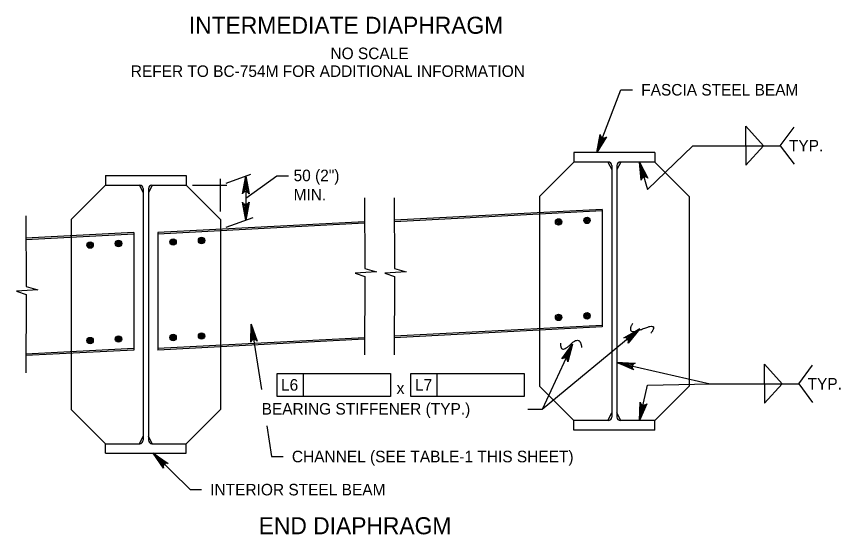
# Model space of a CAD drawing. Extents: x 638175 to 640495, y 294277 to 298435.
# Drawn here: x 639679.1 to 639893, y 297553.5 to 297688 of the extents above; entities that cross this region are included whole.
import ezdxf

# ---------------------------------------------------------------- set-up
doc = ezdxf.new("R2010")
doc.units = 0
for name, color, linetype in [('2', 7, 'Continuous'), ('3', 7, 'Continuous'), ('4', 7, 'Continuous'), ('5', 7, 'Continuous')]:
    doc.layers.add(name, color=color, linetype=linetype)

msp = doc.modelspace()

# ---------------------------------------------------------------- linework, layer by layer
at = {"layer": '2'}
for points in [[(639829.7, 297652.73), (639830.57, 297657.39), (639830.67, 297656.97), (639830.9, 297656.68), (639831.17, 297656.52), (639831.48, 297656.46), (639831.84, 297656.52), (639832.2, 297656.76), (639829.7, 297652.73), (639831.84, 297656.52), (639831.48, 297656.46), (639829.7, 297652.73), (639831.17, 297656.52), (639830.9, 297656.68), (639829.7, 297652.73), (639830.67, 297656.97)], [(639840.81, 297650.23), (639842.94, 297646), (639842.6, 297646.27), (639842.25, 297646.36), (639841.93, 297646.33), (639841.65, 297646.19), (639841.4, 297645.92), (639841.26, 297645.51), (639840.81, 297650.23), (639841.4, 297645.92), (639841.65, 297646.19), (639840.81, 297650.23), (639841.93, 297646.33), (639842.25, 297646.36), (639840.81, 297650.23), (639842.6, 297646.27)], [(639738.58, 297646.6), (639739.45, 297641.94), (639739.2, 297642.3), (639738.89, 297642.48), (639738.58, 297642.54), (639738.27, 297642.48), (639737.95, 297642.3), (639737.71, 297641.94), (639738.58, 297646.6), (639737.95, 297642.3), (639738.27, 297642.48), (639738.58, 297646.6), (639738.58, 297642.54), (639738.89, 297642.48), (639738.58, 297646.6), (639739.2, 297642.3)], [(639738.58, 297635.14), (639737.71, 297639.8), (639737.95, 297639.45), (639738.27, 297639.26), (639738.58, 297639.21), (639738.89, 297639.26), (639739.2, 297639.45), (639739.45, 297639.8), (639738.58, 297635.14), (639739.2, 297639.45), (639738.89, 297639.26), (639738.58, 297635.14), (639738.58, 297639.21), (639738.27, 297639.26), (639738.58, 297635.14), (639737.95, 297639.45)], [(639740.01, 297608.14), (639741.58, 297603.67), (639741.28, 297603.98), (639740.95, 297604.12), (639740.63, 297604.12), (639740.33, 297604.02), (639740.05, 297603.79), (639739.86, 297603.4), (639740.01, 297608.14), (639740.05, 297603.79), (639740.33, 297604.02), (639740.01, 297608.14), (639740.63, 297604.12), (639740.95, 297604.12), (639740.01, 297608.14), (639741.28, 297603.98)], [(639840.87, 297606.86), (639837.83, 297603.22), (639837.95, 297603.64), (639837.89, 297604), (639837.73, 297604.28), (639837.49, 297604.48), (639837.15, 297604.61), (639836.72, 297604.57), (639840.87, 297606.86), (639837.15, 297604.61), (639837.49, 297604.48), (639840.87, 297606.86), (639837.73, 297604.28), (639837.89, 297604), (639840.87, 297606.86), (639837.95, 297603.64)], [(639823.37, 297602.94), (639822.21, 297598.35), (639822.13, 297598.78), (639821.93, 297599.07), (639821.67, 297599.26), (639821.36, 297599.34), (639821, 297599.3), (639820.62, 297599.08), (639823.37, 297602.94), (639821, 297599.3), (639821.36, 297599.34), (639823.37, 297602.94), (639821.67, 297599.26), (639821.93, 297599.07), (639823.37, 297602.94), (639822.13, 297598.78)], [(639834.95, 297598.16), (639839.68, 297597.97), (639839.28, 297597.81), (639839.03, 297597.55), (639838.91, 297597.25), (639838.89, 297596.93), (639839, 297596.59), (639839.3, 297596.27), (639834.95, 297598.16), (639839, 297596.59), (639838.89, 297596.93), (639834.95, 297598.16), (639838.91, 297597.25), (639839.03, 297597.55), (639834.95, 297598.16), (639839.28, 297597.81)], [(639840.81, 297583.08), (639840.98, 297587.82), (639841.14, 297587.42), (639841.41, 297587.17), (639841.7, 297587.05), (639842.01, 297587.03), (639842.36, 297587.14), (639842.68, 297587.44), (639840.81, 297583.08), (639842.36, 297587.14), (639842.01, 297587.03), (639840.81, 297583.08), (639841.7, 297587.05), (639841.41, 297587.17), (639840.81, 297583.08), (639841.14, 297587.42)], [(639714.52, 297574.57), (639718.46, 297571.93), (639718.03, 297572), (639717.68, 297571.91), (639717.42, 297571.72), (639717.24, 297571.46), (639717.15, 297571.11), (639717.23, 297570.68), (639714.52, 297574.57), (639717.15, 297571.11), (639717.24, 297571.46), (639714.52, 297574.57), (639717.42, 297571.72), (639717.68, 297571.91), (639714.52, 297574.57), (639718.03, 297572)]]:
    msp.add_lwpolyline(points, dxfattribs=at)
at = {"layer": '3'}
for p, q in [((639829.7, 297652.73), (639835.99, 297669.01)), ((639835.99, 297669.01), (639838.99, 297669.01)), ((639868.42, 297654.48), (639868.42, 297659.56)), ((639868.42, 297659.56), (639872.96, 297654.48)), ((639877.33, 297654.48), (639880.9, 297659.32)), ((639842.88, 297643.07), (639854.63, 297654.48)), ((639854.63, 297654.48), (639877.33, 297654.48)), ((639868.42, 297649.39), (639872.96, 297654.48)), ((639868.42, 297654.48), (639868.42, 297649.39)), ((639877.33, 297654.48), (639880.9, 297649.64)), ((639840.81, 297650.23), (639842.88, 297643.07)), ((639732.03, 297637.38), (639732.03, 297645.83)), ((639733.5, 297644.75), (639739.89, 297647.08)), ((639738.58, 297640.87), (639746.68, 297646.62)), ((639738.58, 297646.6), (639738.58, 297635.14)), ((639746.68, 297646.62), (639749.68, 297646.62)), ((639724.72, 297644.22), (639733.64, 297644.22)), ((639769.43, 297640.9), (639769.49, 297622.55)), ((639777.15, 297640.9), (639777.21, 297622.55)), ((639681.52, 297636.24), (639681.58, 297617.89)), ((639733.5, 297633.3), (639740.49, 297635.84)), ((639769.49, 297622.55), (639772.5, 297621.67)), ((639777.21, 297622.55), (639780.22, 297621.67)), ((639772.5, 297621.67), (639766.98, 297621.36)), ((639766.98, 297621.36), (639769.49, 297620.5)), ((639769.49, 297620.5), (639769.37, 297600.15)), ((639780.22, 297621.67), (639774.7, 297621.36)), ((639774.7, 297621.36), (639777.21, 297620.5)), ((639777.21, 297620.5), (639777.08, 297600.15)), ((639684.59, 297617.01), (639679.07, 297616.7)), ((639679.07, 297616.7), (639681.58, 297615.84)), ((639681.58, 297615.84), (639681.46, 297595.49)), ((639681.58, 297617.89), (639684.59, 297617.01)), ((639740.01, 297608.14), (639742.63, 297591.12)), ((639840.87, 297606.86), (639815.51, 297585.97)), ((639823.37, 297602.94), (639815.51, 297585.97)), ((639834.95, 297598.16), (639859.12, 297592.63)), ((639873.26, 297592.63), (639873.26, 297597.71)), ((639873.26, 297597.71), (639877.8, 297592.63)), ((639882.17, 297592.63), (639885.74, 297597.47)), ((639746.73, 297595.26), (639776.13, 297595.26)), ((639746.73, 297589.36), (639746.73, 297595.26)), ((639753.58, 297589.36), (639753.58, 297595.26)), ((639776.13, 297595.26), (639776.13, 297589.36)), ((639781.43, 297595.26), (639810.83, 297595.26)), ((639781.43, 297589.36), (639781.43, 297595.26)), ((639788.28, 297589.36), (639788.28, 297595.26)), ((639810.83, 297595.26), (639810.83, 297589.36)), ((639842.88, 297592.28), (639859.12, 297592.63)), ((639859.12, 297592.63), (639882.17, 297592.63)), ((639873.26, 297592.63), (639873.26, 297587.55)), ((639873.26, 297587.55), (639877.8, 297592.63)), ((639882.17, 297592.63), (639885.74, 297587.79)), ((639840.81, 297583.08), (639842.88, 297592.28)), ((639776.13, 297589.36), (639746.73, 297589.36)), ((639810.83, 297589.36), (639781.43, 297589.36)), ((639815.51, 297585.97), (639811.84, 297585.97)), ((639744.08, 297581.72), (639745.3, 297573.73)), ((639714.52, 297574.57), (639724.12, 297565.13)), ((639745.31, 297573.73), (639748.31, 297573.73)), ((639724.12, 297565.13), (639727.12, 297565.13))]:
    msp.add_line(p, q, dxfattribs=at)
for points in [[(639831.25, 297655.35), (639830.32, 297655.71), (639829.7, 297652.73)], [(639841.16, 297647.21), (639842.12, 297647.49), (639840.8, 297650.23)], [(639738.08, 297643.6), (639739.08, 297643.6), (639738.58, 297646.6)], [(639738.08, 297638.14), (639739.08, 297638.14), (639738.58, 297635.14)], [(639739.97, 297605.1), (639740.96, 297605.25), (639740.01, 297608.14)], [(639837.76, 297597), (639837.98, 297597.98), (639834.95, 297598.16)], [(639841.95, 297585.9), (639840.97, 297586.12), (639840.8, 297583.08)], [(639716.31, 297572.11), (639717.01, 297572.82), (639714.52, 297574.57)]]:
    msp.add_lwpolyline(points, close=True, dxfattribs=at)
for points in [[(639838.97, 297608.31), (639837.13, 297605.02), (639845.93, 297608.68), (639843.73, 297605.75)], [(639820.27, 297603.18), (639820.27, 297600.25), (639825.4, 297605.38), (639825.77, 297602.08)]]:
    msp.add_open_spline(points, degree=2, dxfattribs=at)
at = {"layer": '4'}
for p, q in [((639844.74, 297652.73), (639823.77, 297652.73)), ((639823.77, 297650.23), (639814.87, 297641.32)), ((639832.68, 297650.23), (639823.77, 297650.23)), ((639832.58, 297650.23), (639833.57, 297648.26)), ((639835.93, 297650.23), (639834.95, 297648.26)), ((639844.74, 297650.23), (639835.83, 297650.23)), ((639844.74, 297650.23), (639853.65, 297641.32)), ((639833.57, 297649.34), (639833.57, 297583.97)), ((639834.95, 297649.34), (639834.95, 297583.97)), ((639702.16, 297646.72), (639723.13, 297646.72)), ((639702.16, 297644.22), (639693.26, 297635.31)), ((639702.16, 297644.22), (639711.07, 297644.22)), ((639710.97, 297644.22), (639711.96, 297642.25)), ((639714.32, 297644.22), (639713.33, 297642.25)), ((639714.22, 297644.22), (639723.13, 297644.22)), ((639723.13, 297644.22), (639732.03, 297635.31)), ((639711.96, 297643.33), (639711.96, 297577.96)), ((639713.33, 297643.33), (639713.33, 297577.96)), ((639814.87, 297641.32), (639814.87, 297637.08)), ((639853.65, 297641.32), (639853.65, 297591.99)), ((639831.11, 297637.93), (639831.11, 297607.42)), ((639693.26, 297635.31), (639693.26, 297631.07)), ((639732.03, 297635.31), (639732.03, 297632.76)), ((639814.87, 297637.08), (639814.87, 297606.57)), ((639693.26, 297631.07), (639693.26, 297600.56)), ((639709.5, 297631.91), (639709.5, 297601.4)), ((639715.8, 297631.91), (639715.8, 297601.4)), ((639732.03, 297632.76), (639732.03, 297602.25)), ((639814.87, 297606.57), (639814.87, 297591.99)), ((639732.03, 297602.25), (639732.03, 297585.98)), ((639693.26, 297600.56), (639693.26, 297585.98)), ((639814.87, 297591.99), (639823.77, 297583.08)), ((639844.74, 297583.08), (639853.65, 297591.99)), ((639693.26, 297585.98), (639702.16, 297577.07)), ((639723.13, 297577.07), (639732.03, 297585.98)), ((639832.58, 297583.08), (639833.57, 297585.05)), ((639835.93, 297583.08), (639834.95, 297585.05)), ((639832.68, 297583.08), (639823.77, 297583.08)), ((639844.74, 297583.08), (639835.83, 297583.08)), ((639844.74, 297580.58), (639823.77, 297580.58)), ((639710.97, 297577.07), (639711.96, 297579.04)), ((639714.32, 297577.07), (639713.33, 297579.04)), ((639702.16, 297577.07), (639711.07, 297577.07)), ((639714.22, 297577.07), (639723.13, 297577.07)), ((639702.16, 297574.57), (639723.13, 297574.57))]:
    msp.add_line(p, q, dxfattribs=at)
for centre, radius in [((639819.79, 297634.67), 0.833), ((639819.79, 297634.67), 0.625), ((639827.17, 297635.07), 0.833), ((639827.17, 297635.07), 0.625), ((639827.17, 297635.07), 0.417), ((639827.17, 297635.07), 0.208), ((639819.79, 297634.67), 0.417), ((639819.79, 297634.67), 0.208), ((639819.79, 297609.87), 0.833), ((639819.79, 297609.87), 0.625), ((639819.79, 297609.87), 0.417), ((639819.79, 297609.87), 0.208), ((639827.17, 297610.27), 0.833), ((639827.17, 297610.27), 0.625), ((639827.17, 297610.27), 0.417), ((639827.17, 297610.27), 0.208)]:
    msp.add_circle(centre, radius, dxfattribs=at)
for centre, start, end in [((639832.68, 297649.34), 0, 90), ((639835.84, 297649.34), 90, 180), ((639711.07, 297643.33), 0, 90), ((639714.22, 297643.33), 90, 180), ((639832.68, 297583.98), 270, 0), ((639835.84, 297583.98), 180, 270), ((639711.07, 297577.96), 270, 0), ((639714.22, 297577.96), 180, 270)]:
    msp.add_arc(centre, 0.889, start, end, dxfattribs=at)
at = {"layer": '5'}
for p, q in [((639823.77, 297652.73), (639823.77, 297650.23)), ((639844.74, 297652.73), (639844.74, 297650.23)), ((639702.16, 297646.72), (639702.16, 297644.22)), ((639723.13, 297646.72), (639723.13, 297644.22)), ((639831.11, 297637.93), (639777.17, 297635.11)), ((639831.11, 297637.53), (639777.17, 297634.72)), ((639769.45, 297634.71), (639715.8, 297631.91)), ((639769.45, 297634.32), (639715.8, 297631.52)), ((639709.5, 297631.91), (639681.54, 297630.46)), ((639709.5, 297631.52), (639681.54, 297630.06)), ((639831.11, 297607.81), (639777.11, 297605)), ((639831.11, 297607.42), (639777.11, 297604.6)), ((639769.4, 297604.59), (639715.8, 297601.8)), ((639769.4, 297604.2), (639715.8, 297601.4)), ((639709.5, 297601.8), (639681.49, 297600.33)), ((639709.5, 297601.4), (639681.49, 297599.94)), ((639823.77, 297580.58), (639823.77, 297583.08)), ((639844.74, 297580.58), (639844.74, 297583.08)), ((639702.16, 297574.57), (639702.16, 297577.07)), ((639723.13, 297574.57), (639723.13, 297577.07))]:
    msp.add_line(p, q, dxfattribs=at)
for centre, radius in [((639698.18, 297628.66), 0.833), ((639698.18, 297628.66), 0.625), ((639698.18, 297628.66), 0.417), ((639698.18, 297628.66), 0.208), ((639705.56, 297629.06), 0.833), ((639705.56, 297629.06), 0.625), ((639705.56, 297629.06), 0.417), ((639705.56, 297629.06), 0.208), ((639719.73, 297629.46), 0.833), ((639719.73, 297629.46), 0.625), ((639719.73, 297629.46), 0.417), ((639719.73, 297629.46), 0.208), ((639727.11, 297629.84), 0.833), ((639727.11, 297629.84), 0.625), ((639727.11, 297629.84), 0.417), ((639727.11, 297629.84), 0.208), ((639719.73, 297604.66), 0.833), ((639719.73, 297604.66), 0.625), ((639727.11, 297605.04), 0.833), ((639727.11, 297605.04), 0.625), ((639727.11, 297605.04), 0.417), ((639727.11, 297605.04), 0.208), ((639698.18, 297603.86), 0.833), ((639698.18, 297603.86), 0.625), ((639698.18, 297603.86), 0.417), ((639698.18, 297603.86), 0.208), ((639705.56, 297604.26), 0.833), ((639705.56, 297604.26), 0.625), ((639705.56, 297604.26), 0.417), ((639705.56, 297604.26), 0.208), ((639719.73, 297604.66), 0.417), ((639719.73, 297604.66), 0.208)]:
    msp.add_circle(centre, radius, dxfattribs=at)

# ---------------------------------------------------------------- texts
at = {"layer": '3'}
for s, height, p in [('INTERMEDIATE DIAPHRAGM', 4.4292, (639723.81, 297683.55)), ('NO SCALE', 3, (639760.57, 297676.96)), ('REFER TO BC-754M FOR ADDITIONAL INFORMATION', 3, (639708.73, 297672.34)), ('FASCIA STEEL BEAM', 3, (639841.24, 297667.51)), ('TYP.', 3, (639879.58, 297652.98)), ('50 (2")', 3, (639751, 297645.25)), ('MIN. ', 3, (639751, 297640.25)), ('L6', 3, (639747.74, 297590.84)), ('x', 3, (639777.75, 297590.01)), ('L7', 3, (639782.52, 297590.84)), ('TYP.', 3, (639884.42, 297591.13)), ('BEARING STIFFENER (TYP.)', 3, (639742.7, 297584.62)), ('CHANNEL (SEE TABLE-1 THIS SHEET)', 3, (639750.56, 297572.23)), ('INTERIOR STEEL BEAM', 3, (639729.37, 297563.63)), ('END DIAPHRAGM', 4.4292, (639741.94, 297553.53))]:
    msp.add_text(s, height=height, dxfattribs=at).set_placement(p)

doc.saveas('drawing.dxf')
